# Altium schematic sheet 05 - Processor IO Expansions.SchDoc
size B; CompanyName: Microchip Technology Inc.; Organization: Microchip Technology; Address1: 2355 West Chandler Blvd.; Address2: Chandler, AZ  85224; Address4: USA; DocumentNumber: 5; SheetNumber: 5; SheetTotal: 13; SheetTitle: Processor IO Expansions
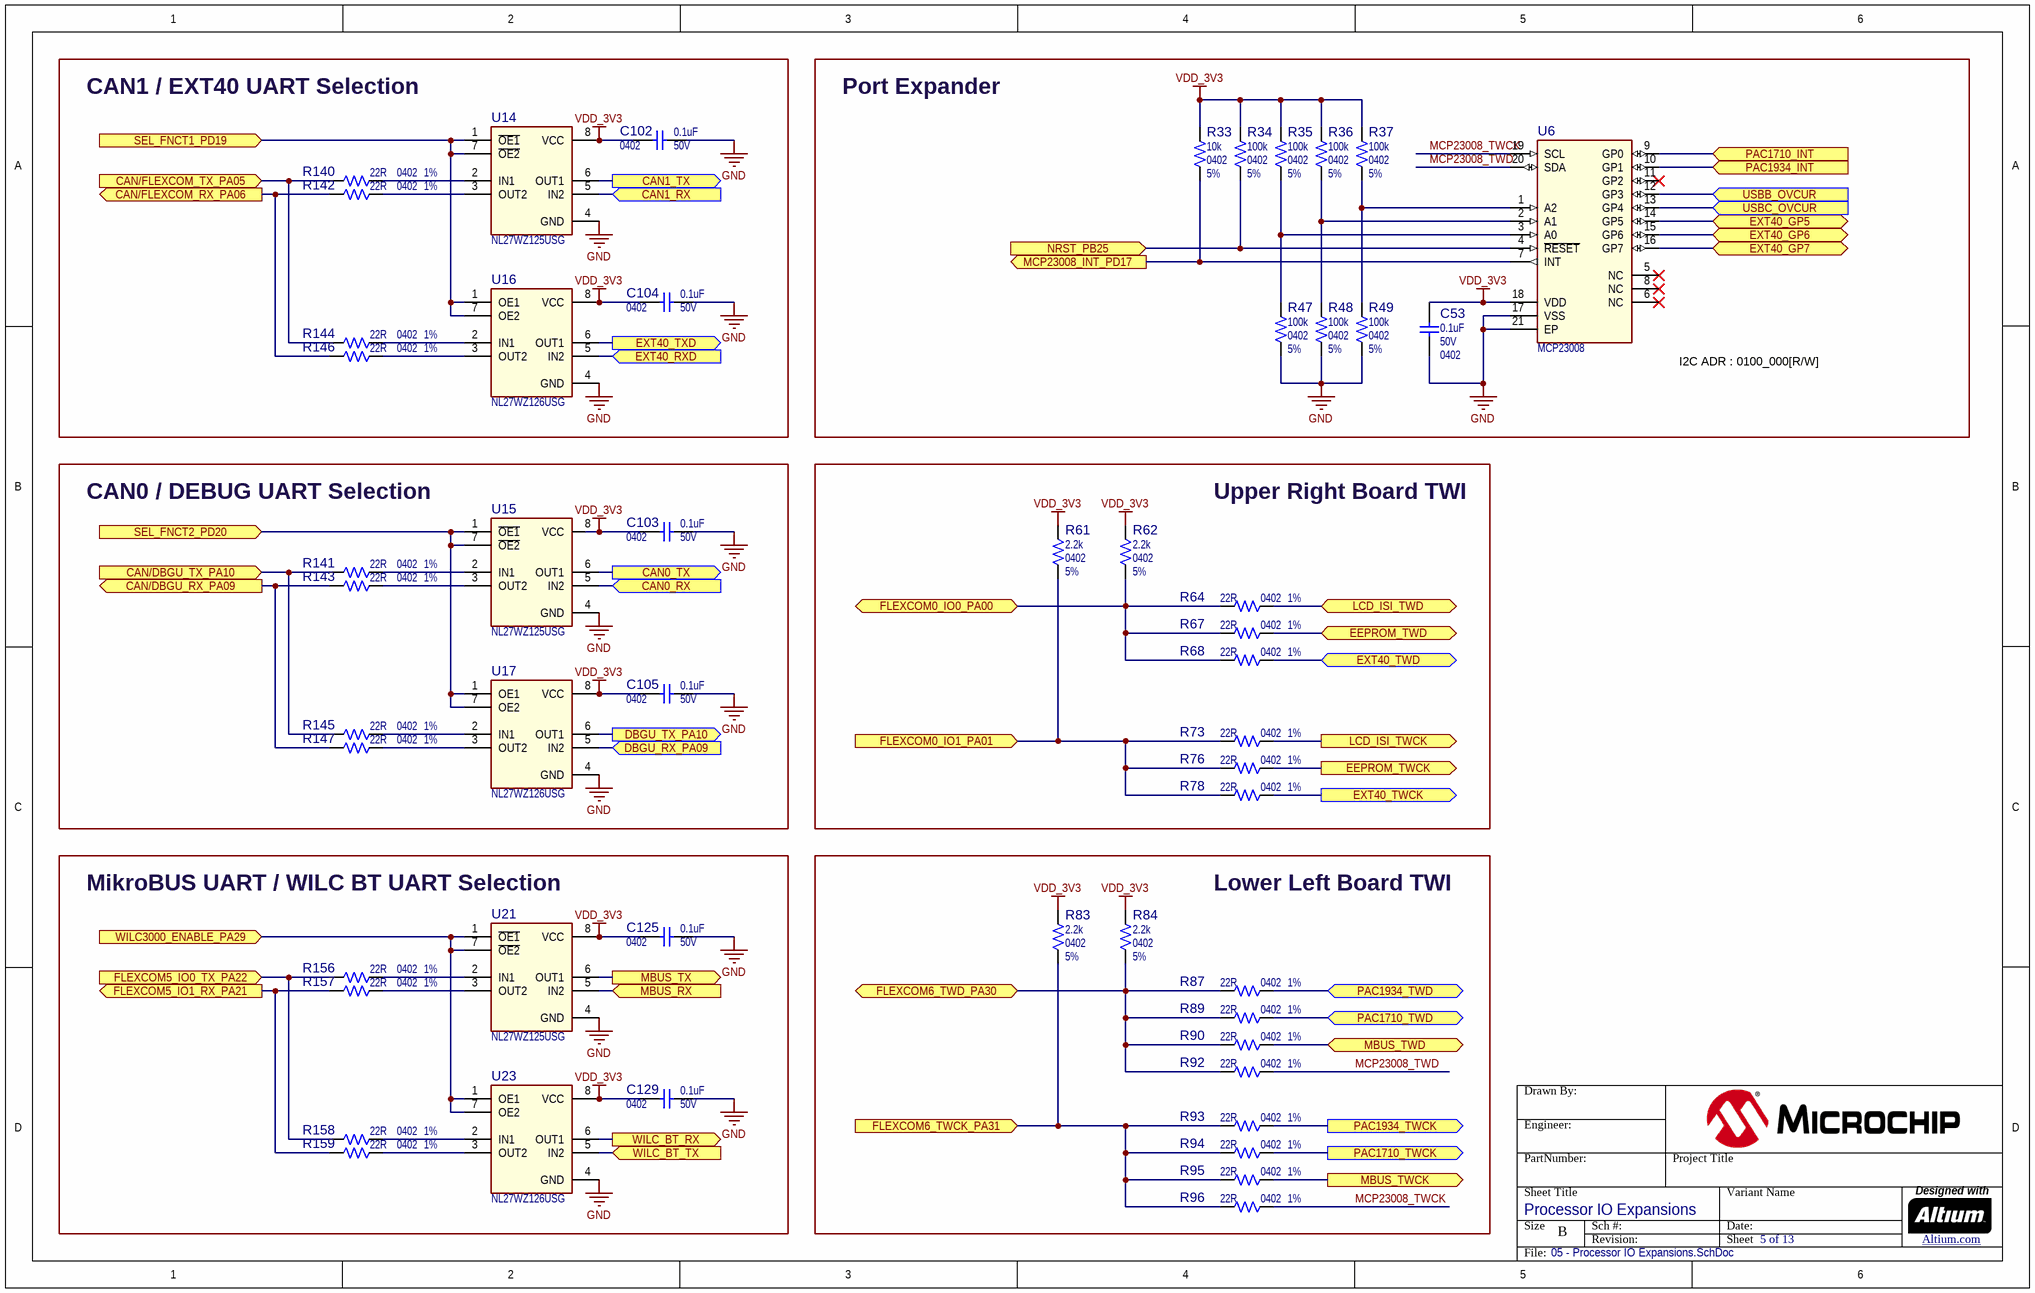
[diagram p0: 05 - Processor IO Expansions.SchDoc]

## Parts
?  (no value)  (graphical)
C53  value 0.1uF  Voltage: 50V  Package: 0402  [CAP_C_0402]  (hidden comment: Capacitor NP)
C102  value 0.1uF  Voltage: 50V  Package: 0402  [CAP_C_0402]  (hidden comment: Capacitor NP)
C103  value 0.1uF  Voltage: 50V  Package: 0402  [CAP_C_0402]  (hidden comment: Capacitor NP)
C104  value 0.1uF  Voltage: 50V  Package: 0402  [CAP_C_0402]  (hidden comment: Capacitor NP)
C105  value 0.1uF  Voltage: 50V  Package: 0402  [CAP_C_0402]  (hidden comment: Capacitor NP)
C125  value 0.1uF  Voltage: 50V  Package: 0402  [CAP_C_0402]  (hidden comment: Capacitor NP)
C129  value 0.1uF  Voltage: 50V  Package: 0402  [CAP_C_0402]  (hidden comment: Capacitor NP)
R33  value 10k  Package: 0402  Tolerance: 5%  [RES_C_0402]  (hidden comment: Resistor)
R34  value 100k  Package: 0402  Tolerance: 5%  [RES_C_0402]  (hidden comment: Resistor)
R35  value 100k  Package: 0402  Tolerance: 5%  [RES_C_0402]  (hidden comment: Resistor)
R36  value 100k  Package: 0402  Tolerance: 5%  [RES_C_0402]  (hidden comment: Resistor)
R37  value 100k  Package: 0402  Tolerance: 5%  [RES_C_0402]  (hidden comment: Resistor)
R47  value 100k  Package: 0402  Tolerance: 5%  [RES_C_0402]  (hidden comment: Resistor)
R48  value 100k  Package: 0402  Tolerance: 5%  [RES_C_0402]  (hidden comment: Resistor)
R49  value 100k  Package: 0402  Tolerance: 5%  [RES_C_0402]  (hidden comment: Resistor)
R61  value 2.2k  Package: 0402  Tolerance: 5%  [RES_C_0402]  (hidden comment: Resistor)
R62  value 2.2k  Package: 0402  Tolerance: 5%  [RES_C_0402]  (hidden comment: Resistor)
R64  value 22R  Package: 0402  Tolerance: 1%  [RES_C_0402]  (hidden comment: Resistor)
R67  value 22R  Package: 0402  Tolerance: 1%  [RES_C_0402]  (hidden comment: Resistor)
R68  value 22R  Package: 0402  Tolerance: 1%  [RES_C_0402]  (hidden comment: Resistor)
R73  value 22R  Package: 0402  Tolerance: 1%  [RES_C_0402]  (hidden comment: Resistor)
R76  value 22R  Package: 0402  Tolerance: 1%  [RES_C_0402]  (hidden comment: Resistor)
R78  value 22R  Package: 0402  Tolerance: 1%  [RES_C_0402]  (hidden comment: Resistor)
R83  value 2.2k  Package: 0402  Tolerance: 5%  [RES_C_0402]  (hidden comment: Resistor)
R84  value 2.2k  Package: 0402  Tolerance: 5%  [RES_C_0402]  (hidden comment: Resistor)
R87  value 22R  Package: 0402  Tolerance: 1%  [RES_C_0402]  (hidden comment: Resistor)
R89  value 22R  Package: 0402  Tolerance: 1%  [RES_C_0402]  (hidden comment: Resistor)
R90  value 22R  Package: 0402  Tolerance: 1%  [RES_C_0402]  (hidden comment: Resistor)
R92  value 22R  Package: 0402  Tolerance: 1%  [RES_C_0402]  (hidden comment: Resistor)
R93  value 22R  Package: 0402  Tolerance: 1%  [RES_C_0402]  (hidden comment: Resistor)
R94  value 22R  Package: 0402  Tolerance: 1%  [RES_C_0402]  (hidden comment: Resistor)
R95  value 22R  Package: 0402  Tolerance: 1%  [RES_C_0402]  (hidden comment: Resistor)
R96  value 22R  Package: 0402  Tolerance: 1%  [RES_C_0402]  (hidden comment: Resistor)
R140  value 22R  Package: 0402  Tolerance: 1%  [RES_C_0402]  (hidden comment: Resistor)
R141  value 22R  Package: 0402  Tolerance: 1%  [RES_C_0402]  (hidden comment: Resistor)
R142  value 22R  Package: 0402  Tolerance: 1%  [RES_C_0402]  (hidden comment: Resistor)
R143  value 22R  Package: 0402  Tolerance: 1%  [RES_C_0402]  (hidden comment: Resistor)
R144  value 22R  Package: 0402  Tolerance: 1%  [RES_C_0402]  (hidden comment: Resistor)
R145  value 22R  Package: 0402  Tolerance: 1%  [RES_C_0402]  (hidden comment: Resistor)
R146  value 22R  Package: 0402  Tolerance: 1%  [RES_C_0402]  (hidden comment: Resistor)
R147  value 22R  Package: 0402  Tolerance: 1%  [RES_C_0402]  (hidden comment: Resistor)
R156  value 22R  Package: 0402  Tolerance: 1%  [RES_C_0402]  (hidden comment: Resistor)
R157  value 22R  Package: 0402  Tolerance: 1%  [RES_C_0402]  (hidden comment: Resistor)
R158  value 22R  Package: 0402  Tolerance: 1%  [RES_C_0402]  (hidden comment: Resistor)
R159  value 22R  Package: 0402  Tolerance: 1%  [RES_C_0402]  (hidden comment: Resistor)
U6  value MCP23008  [QFN-20_4x4]  (hidden comment: MCP23008 QFN-20)
U14  value NL27WZ125USG  [US-8]  (hidden comment: NL27WZ125 US-8)
U15  value NL27WZ125USG  [US-8]  (hidden comment: NL27WZ125 US-8)
U16  value NL27WZ126USG  [US-8]  (hidden comment: NL27WZ126 US-8)
U17  value NL27WZ126USG  [US-8]  (hidden comment: NL27WZ126 US-8)
U21  value NL27WZ125USG  [US-8]  (hidden comment: NL27WZ125 US-8)
U23  value NL27WZ126USG  [US-8]  (hidden comment: NL27WZ126 US-8)

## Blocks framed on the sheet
CAN1 / EXT40 UART Selection: C102 C104 R140 R142 R144 R146 U14 U16
Port Expander: C53 R33-R37 R47-R49 U6
CAN0 / DEBUG UART Selection: C103 C105 R141 R143 R145 R147 U15 U17
Upper Right Board TWI: R61 R62 R64 R67 R68 R73 R76 R78
MikroBUS UART / WILC BT UART Selection: C125 C129 R156-R159 U21 U23
Lower Left Board TWI: R83 R84 R87 R89 R90 R92-R96

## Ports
CAN0_RX (in), CAN0_TX (out), CAN1_RX (in), CAN1_TX (out), CAN/DBGU_RX_PA09 (out), CAN/DBGU_TX_PA10 (in), CAN/FLEXCOM_RX_PA06 (out), CAN/FLEXCOM_TX_PA05 (in), DBGU_RX_PA09 (in), DBGU_TX_PA10 (out), EEPROM_TWCK (out), EEPROM_TWD (bidir), EXT40_GP5 (bidir), EXT40_GP6 (bidir), EXT40_GP7 (bidir), EXT40_RXD (in), EXT40_TWCK (out), EXT40_TWD (bidir), EXT40_TXD (out), FLEXCOM0_IO0_PA00 (bidir), FLEXCOM0_IO1_PA01 (in), FLEXCOM5_IO0_TX_PA22 (in), FLEXCOM5_IO1_RX_PA21 (out), FLEXCOM6_TWCK_PA31 (in), FLEXCOM6_TWD_PA30 (bidir), LCD_ISI_TWCK (out), LCD_ISI_TWD (bidir), MBUS_RX (in), MBUS_TWCK (out), MBUS_TWD (bidir), MBUS_TX (out), MCP23008_INT_PD17 (out), NRST_PB25 (in), PAC1710_INT (in), PAC1710_TWCK (out), PAC1710_TWD (bidir), PAC1934_INT (in), PAC1934_TWCK (out), PAC1934_TWD (bidir), SEL_FNCT1_PD19 (in), SEL_FNCT2_PD20 (in), USBB_OVCUR (in), USBC_OVCUR (in), WILC3000_ENABLE_PA29 (in), WILC_BT_RX (out), WILC_BT_TX (in)

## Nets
GND: C53.2 C102.2 C103.2 C104.2 C105.2 C125.2 C129.2 R47.1 R48.1 R49.1 U6.17(VSS) U6.21(EP) U14.4(GND) U15.4(GND) U16.4(GND) U17.4(GND) U21.4(GND) U23.4(GND)
VDD_3V3: C53.1 C102.1 C103.1 C104.1 C105.1 C125.1 C129.1 R33.2 R34.2 R35.2 R36.2 R37.2 R61.2 R62.2 R83.2 R84.2 U6.18(VDD) U14.8(VCC) U15.8(VCC) U16.8(VCC) U17.8(VCC) U21.8(VCC) U23.8(VCC)
CAN0_RX: U15.5(IN2) ; port CAN0_RX
CAN0_TX: U15.6(OUT1) ; port CAN0_TX
CAN1_RX: U14.5(IN2) ; port CAN1_RX
CAN1_TX: U14.6(OUT1) ; port CAN1_TX
CAN/DBGU_RX_PA09: R143.2 R147.2 ; port CAN/DBGU_RX_PA09
CAN/DBGU_TX_PA10: R141.2 R145.2 ; port CAN/DBGU_TX_PA10
CAN/FLEXCOM_RX_PA06: R142.2 R146.2 ; port CAN/FLEXCOM_RX_PA06
CAN/FLEXCOM_TX_PA05: R140.2 R144.2 ; port CAN/FLEXCOM_TX_PA05
DBGU_RX_PA09: U17.5(IN2) ; port DBGU_RX_PA09
DBGU_TX_PA10: U17.6(OUT1) ; port DBGU_TX_PA10
EEPROM_TWCK: R76.2 ; port EEPROM_TWCK
EEPROM_TWD: R67.2 ; port EEPROM_TWD
EXT40_GP5: U6.14(GP5) ; port EXT40_GP5
EXT40_GP6: U6.15(GP6) ; port EXT40_GP6
EXT40_GP7: U6.16(GP7) ; port EXT40_GP7
EXT40_RXD: U16.5(IN2) ; port EXT40_RXD
EXT40_TWCK: R78.2 ; port EXT40_TWCK
EXT40_TWD: R68.2 ; port EXT40_TWD
EXT40_TXD: U16.6(OUT1) ; port EXT40_TXD
FLEXCOM0_IO0_PA00: R62.1 R64.1 R67.1 R68.1 ; port FLEXCOM0_IO0_PA00
FLEXCOM0_IO1_PA01: R61.1 R73.1 R76.1 R78.1 ; port FLEXCOM0_IO1_PA01
FLEXCOM5_IO0_TX_PA22: R156.2 R158.2 ; port FLEXCOM5_IO0_TX_PA22
FLEXCOM5_IO1_RX_PA21: R157.2 R159.2 ; port FLEXCOM5_IO1_RX_PA21
FLEXCOM6_TWCK_PA31: R83.1 R93.1 R94.1 R95.1 R96.1 ; port FLEXCOM6_TWCK_PA31
FLEXCOM6_TWD_PA30: R84.1 R87.1 R89.1 R90.1 R92.1 ; port FLEXCOM6_TWD_PA30
LCD_ISI_TWCK: R73.2 ; port LCD_ISI_TWCK
LCD_ISI_TWD: R64.2 ; port LCD_ISI_TWD
MBUS_RX: U21.5(IN2) ; port MBUS_RX
MBUS_TWCK: R95.2 ; port MBUS_TWCK
MBUS_TWD: R90.2 ; port MBUS_TWD
MBUS_TX: U21.6(OUT1) ; port MBUS_TX
MCP23008_INT_PD17: R33.1 U6.7(INT) ; port MCP23008_INT_PD17
MCP23008_TWCK: R96.2 U6.19(SCL)
MCP23008_TWD: R92.2 U6.20(SDA)
NRST_PB25: R34.1 U6.4(~{RESET}) ; port NRST_PB25
PAC1710_INT: U6.9(GP0) ; port PAC1710_INT
PAC1710_TWCK: R94.2 ; port PAC1710_TWCK
PAC1710_TWD: R89.2 ; port PAC1710_TWD
PAC1934_INT: U6.10(GP1) ; port PAC1934_INT
PAC1934_TWCK: R93.2 ; port PAC1934_TWCK
PAC1934_TWD: R87.2 ; port PAC1934_TWD
SEL_FNCT1_PD19: U14.1(~{OE1}) U14.7(~{OE2}) U16.1(OE1) U16.7(OE2) ; port SEL_FNCT1_PD19
SEL_FNCT2_PD20: U15.1(~{OE1}) U15.7(~{OE2}) U17.1(OE1) U17.7(OE2) ; port SEL_FNCT2_PD20
USBB_OVCUR: U6.12(GP3) ; port USBB_OVCUR
USBC_OVCUR: U6.13(GP4) ; port USBC_OVCUR
WILC3000_ENABLE_PA29: U21.1(~{OE1}) U21.7(~{OE2}) U23.1(OE1) U23.7(OE2) ; port WILC3000_ENABLE_PA29
WILC_BT_RX: U23.6(OUT1) ; port WILC_BT_RX
WILC_BT_TX: U23.5(IN2) ; port WILC_BT_TX
NetR35_1: R35.1 R47.2 U6.3(A0)
NetR36_1: R36.1 R48.2 U6.2(A1)
NetR37_1: R37.1 R49.2 U6.1(A2)
NetR140_1: R140.1 U14.2(IN1)
NetR141_1: R141.1 U15.2(IN1)
NetR142_1: R142.1 U14.3(OUT2)
NetR143_1: R143.1 U15.3(OUT2)
NetR144_1: R144.1 U16.2(IN1)
NetR145_1: R145.1 U17.2(IN1)
NetR146_1: R146.1 U16.3(OUT2)
NetR147_1: R147.1 U17.3(OUT2)
NetR156_1: R156.1 U21.2(IN1)
NetR157_1: R157.1 U21.3(OUT2)
NetR158_1: R158.1 U23.2(IN1)
NetR159_1: R159.1 U23.3(OUT2)

Not connected (* = marked no-connect by the designer): U6 5(NC)* 6(NC)* 8(NC)* 11(GP2)*

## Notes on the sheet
- (near U6) I2C ADR : 0100_000[R/W]

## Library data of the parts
? = Title Block B
C53 C102-C105 C125 C129 = CAP1463: Capacitor; Manufacturer 1: TDK Corporation; Manufacturer Part Number 1: C1005X7R1H104K050BB; Description_: CAP CER 0.1uF 50V 10% X7R SMD 0402; Dev Tools Status: Production; Tolerance: 10%; Temperature Coeffcient: X7R; Type: Ceramic; Owner: Jamus Griego; Populated: YES
R33 = RSMT0439: Manufacturer 1: Vishay; Manufacturer Part Number 1: CRCW040210K0JNED; Description_: RES TKF 10k 5% 1/16W SMD 0402; Dev Tools Status: Production; Voltage: 50V; Temperature Coeffcient: 100ppm/C; Power: 1/16W; Populated: Yes
R34 R47-R49 = RES2196: Manufacturer 1: Yageo; Manufacturer Part Number 1: RC0402JR-07100KL; Description_: RES TKF 100k 5% 1/16W SMD 0402; Dev Tools Status: Design; Temperature Coeffcient: 100ppm/C; Power: 1/16W; Owner: Ilie Galan; Populated: YES
R35-R37 = RES2196: Manufacturer 1: Yageo; Manufacturer Part Number 1: RC0402JR-07100KL; Description_: RES TKF 100k 5% 1/16W SMD 0402; Dev Tools Status: Design; Temperature Coeffcient: 100ppm/C; Power: 1/16W; Owner: Ilie Galan; Populated: DNP
R61 R62 R83 R84 = RES1020: Manufacturer 1: Vishay Dale; Manufacturer Part Number 1: CRCW04022K20JNED; Description_: RES TKF 2.2k 5% 1/16W SMD 0402; Dev Tools Status: Production; Voltage: 50V; Temperature Coeffcient: 200ppm/C; Power: 1/16W; Owner: Tad Ahlvers; Populated: YES
R64 R67 R68 R73 R76 R78 R87 R89 R90 R92-R96 R140-R147 R156-R159 = RES1474: Manufacturer 1: Panasonic Electronic Components; Manufacturer Part Number 1: ERJ-2RKF22R0X; Description_: RES TKF 22R 1% 1/20W SMD 0402; Dev Tools Status: Production; Temperature Coeffcient: 100ppm/C; Circuit Type: Isolated; Power: 1/10W; Owner: Mike Ragsdale; Populated: YES
U6 = MIC2806: I/O Expander; Manufacturer 1: Microchip; Manufacturer Part Number 1: MCP23008T-E/ML; Description_: MCHP INTERFACE GPIO-PORT EXPAND I2C 8-Port MCP23008-E/ML QFN-20; MAPS Description: 8 BIT INPUT/OUTPUT EXPANDER, I2C INTERFACE; Dev Tools Status: Production; MPC: C5BQ1YG4XA00; LeadContent: Pb-FREE; PackingMedia: T/R; Stage: REL; LeadCount: 20; PackageWidth: 4x4x0.9mm; ForceMinOrderQtyMult: True; MinOrderQty: 1; TempRange: -40C to +125C; tblDeviceFamilyID: 1180; OperatingVoltageMin: 1.8; OperatingVoltageMax: 5.5; IOpins: 8; Interface: 524288; Speed: 1.7M; HWAddressPins: 3; ResetPin: Yes; PinCurrent: 25; TotalCurrent: 160; IOVoltageTolerant: VDD
U14 U15 U21 = IC1512: BUFFER DL TRI-ST NON-INV; Manufacturer 1: ON Semiconductor; MCHP-ID: IC1512; Description_: IC BUFFER NL27WZ125USG DUAL TRI-ST NON-INV US-8; Dev Tools Status: Design; Vin: 5V; Owner: Ciprian Abramov; Populated: YES
U16 U17 U23 = IC1514: BUFFER DL TRI-ST NON-INV; Manufacturer 1: ON Semiconductor; MCHP-ID: IC1514; Description_: IC BUFFER NL27WZ126USG DUAL TRI-ST NON-INV US-8; Dev Tools Status: Design; Vin: 5V; Owner: Ciprian Abramov; Populated: YES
